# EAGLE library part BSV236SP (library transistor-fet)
OptiMOS(R)-P Small-Signal-Transistor P-Channel, Enhancement mode, Super Logic Level (2.5 V rated) Source: http://www.infineon.com/upload/Document/BSV236SP_Rev1.3.pdf
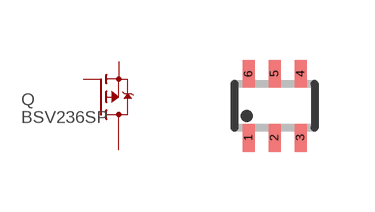
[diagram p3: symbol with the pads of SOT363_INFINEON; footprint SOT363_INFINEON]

Designator prefix Q

## BSV236SP  [SOT363_INFINEON]
1  D  pas
2  D  pas
3  G  pas
4  S  pas
5  D  pas
6  D  pas

## Footprint SOT363_INFINEON (pad centres in mm)
Small Outline Transistor; 6 leads Reflow soldering INFINEON, www.infineon.com/cmc_upload/0/000/010/257/eh_db_5b.pdf
smd 0.3 x 0.7: 1 -0.65,-0.8; 2 0,-0.8; 3 0.65,-0.8; 4 0.65,0.8; 5 0,0.8; 6 -0.65,0.8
